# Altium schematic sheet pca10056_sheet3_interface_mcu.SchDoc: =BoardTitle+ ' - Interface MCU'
size A3; Organization: Nordic Semiconductor; DocumentNumber: 3; SheetNumber: 3; SheetTotal: 6; CompanyName: Nordic Semiconductor; DocumentSize: A3
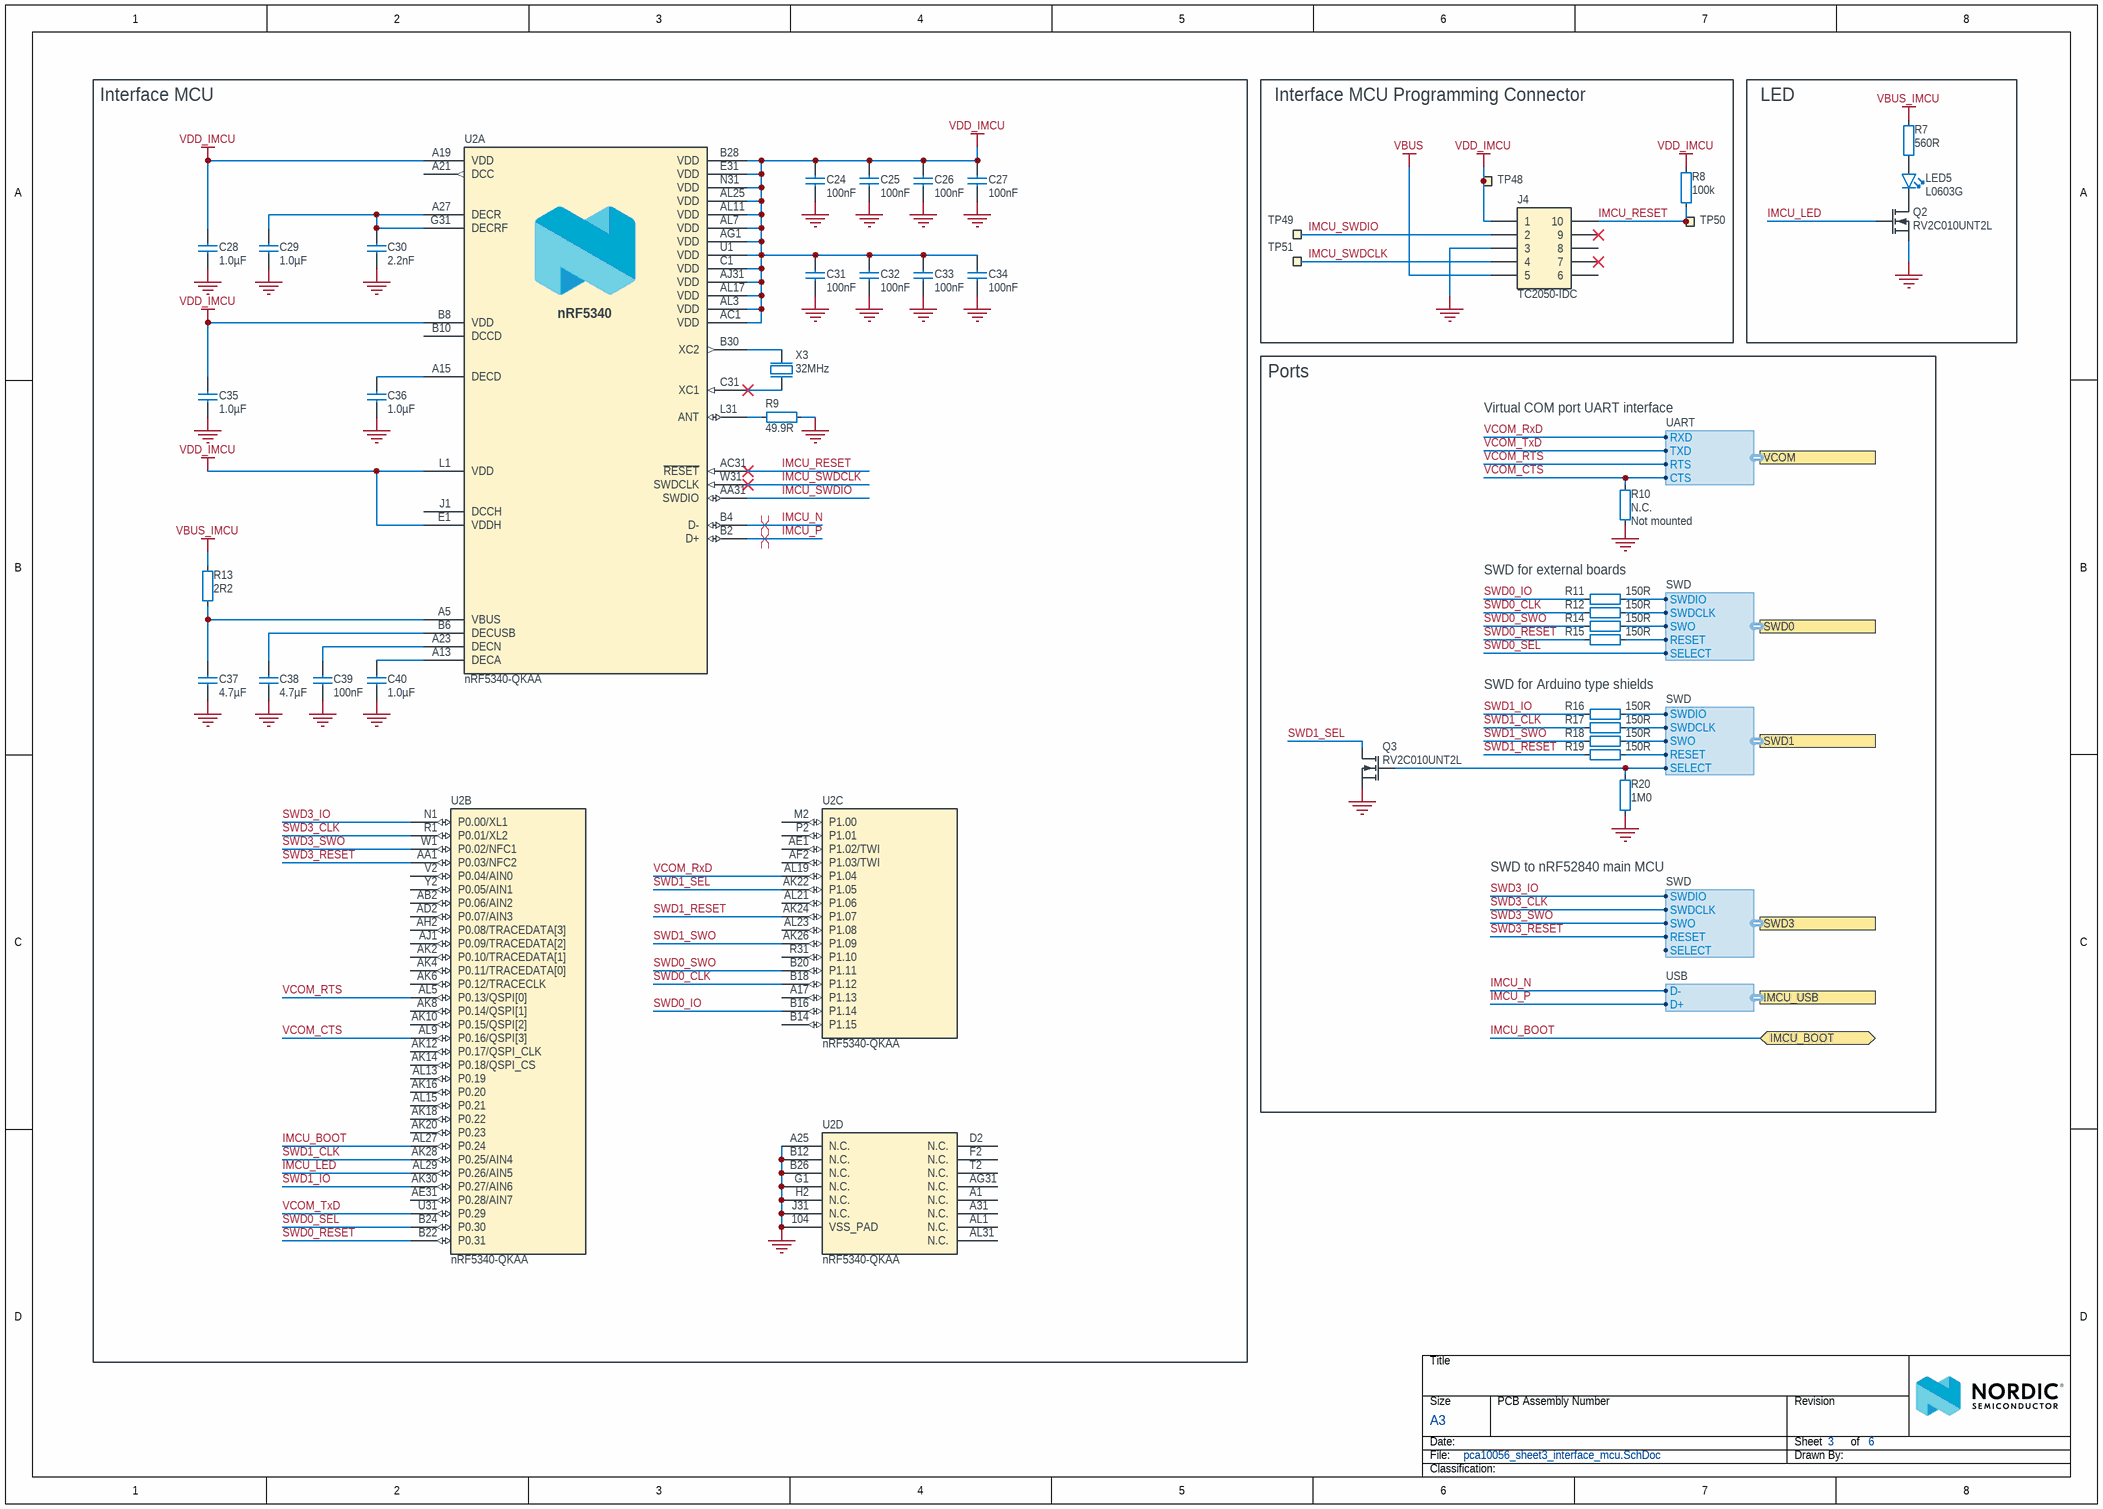
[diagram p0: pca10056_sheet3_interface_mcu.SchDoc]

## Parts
C24  100nF  [CAPC0603X03L_C]
C25  100nF  [CAPC0603X03L_C]
C26  100nF  [CAPC0603X03L_C]
C27  100nF  [CAPC0603X03L_C]
C28  1.0µF  [CAPC1005X04L]
C29  1.0µF  [CAPC1005X04L]
C30  2.2nF  [CAPC0603X03L_C]
C31  100nF  [CAPC0603X03L_C]
C32  100nF  [CAPC0603X03L_C]
C33  100nF  [CAPC0603X03L_C]
C34  100nF  [CAPC0603X03L_C]
C35  1.0µF  [CAPC1005X04L]
C36  1.0µF  [CAPC1005X04L]
C37  4.7µF  [CAPC1608X06L]
C38  4.7µF  [CAPC1608X06L]
C39  100nF  [CAPC0603X03L_C]
C40  1.0µF  [CAPC1005X04L]
J4  TC2050-IDC  [TC2050-IDC-NLFP]  (no BOM)
LED5  L0603G  [LED_0603_G]
Q2  RV2C010UNT2L  [DFN65P100X40-3L]
Q3  RV2C010UNT2L  [DFN65P100X40-3L]
R7  560R  [RESC0603X03L_C]
R8  100k  [RESC0603X03L_C]
R9  49.9R  [RESC0603X03L_C]
R10  N.C.  Assembly: Not mounted  [RESC0603X03L_C_NC]
R11  150R  [RESC0603X03L_C]
R12  150R  [RESC0603X03L_C]
R13  2R2  [RESC0603X03L_C]
R14  150R  [RESC0603X03L_C]
R15  150R  [RESC0603X03L_C]
R16  150R  [RESC0603X03L_C]
R17  150R  [RESC0603X03L_C]
R18  150R  [RESC0603X03L_C]
R19  150R  [RESC0603X03L_C]
R20  1M0  [RESC0603X03L_C]
TP48  Ø1.5mm,SMD  [TP_SMD_D1.5mm]  (value not drawn)  (no BOM)
TP49  Ø1.5mm,SMD  [TP_SMD_D1.5mm]  (value not drawn)  (no BOM)
TP50  Ø1.5mm,SMD  [TP_SMD_D1.5mm]  (value not drawn)  (no BOM)
TP51  Ø1.5mm,SMD  [TP_SMD_D1.5mm]  (value not drawn)  (no BOM)
U2  nRF5340-QKAA  [AQFN40P700X700X85_HS-99N]  (parts A,B,C,D of 4)
X3  32MHz  [BT-XTAL_2016]

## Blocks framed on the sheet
Interface MCU: C24-C40 R9 R13 U2 X3
Interface MCU Programming Connector: J4 R8 TP48-TP51
LED: LED5 Q2 R7
Ports: Q3 R10-R12 R14-R20

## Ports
IMCU_BOOT (bidir), IMCU_USB (harness USB), SWD0 (harness SWD), SWD1 (harness SWD), SWD3 (harness SWD), VCOM (harness UART)

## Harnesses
UART: RTS, CTS, RXD, TXD
SWD: SWDIO, SWDCLK, SWO, RESET, SELECT
USB: D+, D-

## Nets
GND: C24.2 C25.2 C26.2 C27.2 C28.2 C29.1 C30.2 C31.2 C32.2 C33.2 C34.2 C35.1 C36.1 C37.2 C38.2 C39.2 C40.1 J4.3 Q2.2(S) Q3.2(S) R9.2 R10.2 R20.2 U2.104(VSS_PAD) U2.A25(N.C.) U2.B12(N.C.) U2.B26(N.C.) U2.G1(N.C.) U2.H2(N.C.) U2.J31(N.C.) X3.2(GND) X3.4(GND)
VBUS: J4.5
VBUS_IMCU: R7.2 R13.1
VDD_IMCU: C24.1 C25.1 C26.1 C27.1 C28.1 C31.1 C32.1 C33.1 C34.1 C35.2 J4.1 R8.2 TP48.1 U2.A19(VDD) U2.AC1(VDD) U2.AG1(VDD) U2.AJ31(VDD) U2.AL3(VDD) U2.AL7(VDD) U2.AL11(VDD) U2.AL17(VDD) U2.AL25(VDD) U2.B8(VDD) U2.B28(VDD) U2.C1(VDD) U2.E1(VDDH) U2.E31(VDD) U2.L1(VDD) U2.N31(VDD) U2.U1(VDD)
IMCU_BOOT: U2.AL27(P0.24) ; port IMCU_BOOT
IMCU_LED: Q2.1(G) U2.AL29(P0.26/AIN5)
IMCU_N: U2.B4(D-) ; port IMCU_USB.D-
IMCU_P: U2.B2(D+) ; port IMCU_USB.D+
IMCU_RESET: J4.10 R8.1 TP50.1 U2.AC31(~{RESET})
IMCU_SWDCLK: J4.4 TP51.1 U2.W31(SWDCLK)
IMCU_SWDIO: J4.2 TP49.1 U2.AA31(SWDIO)
SWD0_CLK: R12.1 U2.B18(P1.12)
SWD0_IO: R11.1 U2.B16(P1.14)
SWD0_RESET: R15.1 U2.B22(P0.31)
SWD0_SEL: U2.B24(P0.30) ; port SWD0.SELECT
SWD0_SWO: R14.1 U2.B20(P1.11)
SWD1_CLK: R17.1 U2.AK28(P0.25/AIN4)
SWD1_IO: R16.1 U2.AK30(P0.27/AIN6)
SWD1_RESET: R19.1 U2.AK24(P1.07)
SWD1_SEL: Q3.3(D) U2.AK22(P1.05)
SWD1_SWO: R18.1 U2.AK26(P1.09)
SWD3_CLK: U2.R1(P0.01/XL2) ; port SWD3.SWDCLK
SWD3_IO: U2.N1(P0.00/XL1) ; port SWD3.SWDIO
SWD3_RESET: U2.AA1(P0.03/NFC2) ; port SWD3.RESET
SWD3_SWO: U2.W1(P0.02/NFC1) ; port SWD3.SWO
VCOM_CTS: R10.1 U2.AL9(P0.16/QSPI[3]) ; port VCOM.CTS
VCOM_RTS: U2.AL5(P0.13/QSPI[0]) ; port VCOM.RTS
VCOM_RxD: U2.AL19(P1.04) ; port VCOM.RXD
VCOM_TxD: U2.U31(P0.29) ; port VCOM.TXD
NetC29_2: C29.2 C30.1 U2.A27(DECR) U2.G31(DECRF)
NetC36_2: C36.2 U2.A15(DECD)
NetC37_1: C37.1 R13.2 U2.A5(VBUS)
NetC38_1: C38.1 U2.B6(DECUSB)
NetC39_1: C39.1 U2.A23(DECN)
NetC40_2: C40.2 U2.A13(DECA)
NetLED5_1: LED5.1(C) Q2.3(D)
NetLED5_2: LED5.2(A) R7.1
NetQ3_1: Q3.1(G) R20.1 ; port SWD1.SELECT
NetR9_1: R9.1 U2.L31(ANT)
NetR11_2: R11.2 ; port SWD0.SWDIO
NetR12_2: R12.2 ; port SWD0.SWDCLK
NetR14_2: R14.2 ; port SWD0.SWO
NetR15_2: R15.2 ; port SWD0.RESET
NetR16_2: R16.2 ; port SWD1.SWDIO
NetR17_2: R17.2 ; port SWD1.SWDCLK
NetR18_2: R18.2 ; port SWD1.SWO
NetR19_2: R19.2 ; port SWD1.RESET
NetU2_B30: U2.B30(XC2) X3.3(out)
NetU2_C31: U2.C31(XC1) X3.1(inp)

Not connected (* = marked no-connect by the designer): J4 6 7* 8 9*; U2 A1(N.C.) A17(P1.13) A21(DCC) A31(N.C.) AB2(P0.06/AIN2) AD2(P0.07/AIN3) AE1(P1.02/TWI) AE31(P0.28/AIN7) AF2(P1.03/TWI) AG31(N.C.) AH2(P0.08/TRACEDATA[3]) AJ1(P0.09/TRACEDATA[2]) AK2(P0.10/TRACEDATA[1]) AK4(P0.11/TRACEDATA[0]) AK6(P0.12/TRACECLK) AK8(P0.14/QSPI[1]) AK10(P0.15/QSPI[2]) AK12(P0.17/QSPI_CLK) AK14(P0.18/QSPI_CS) AK16(P0.20) AK18(P0.22) AK20(P0.23) AL1(N.C.) AL13(P0.19) AL15(P0.21) AL21(P1.06) AL23(P1.08) AL31(N.C.) B10(DCCD) B14(P1.15) D2(N.C.) F2(N.C.) J1(DCCH) M2(P1.00) P2(P1.01) R31(P1.10) T2(N.C.) V2(P0.04/AIN0) Y2(P0.05/AIN1)

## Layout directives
differential pair: IMCU_N, IMCU_P

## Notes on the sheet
- Virtual COM port UART interface
- SWD for external boards
- SWD for Arduino type shields
- (near R20) SWD to nRF52840 main MCU

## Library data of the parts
C24-C27 C31-C34 C39 = C0201-100n: Capacitor, X5R, ±10%; Manufacturer: N.A.; Part number IPS: 00000001248, 00000002505; Part number Norautron: 262071862; Part number NEMS: 100200078; Pad Count: 2; Note: 16V; Component Status: Active
C28 C29 C35 C36 C40 = C0402-1µ0-6.3V-X5R-10%: Capacitor, X5R, ±10%, 6.3V; Manufacturer: N.A.; Part number Norautron: 26207137; Part number NEMS: 100200498; Pad Count: 2; Component Status: Active
C30 = C0201-2n2: Capacitor, X7R, ±10%, 10V; Manufacturer: N.A.; Part number IPS: 00000001778; Part number Norautron: 26470002; Part number NEMS: 100200060; Pad Count: 2; Component Status: Active
C37 = C0603-4µ7-10V-X7S: Capacitor, X7S, ±10%, 10V; Manufacturer: N.A.; Part number IPS: 00000001779; Part number NEMS: 100200351; Pad Count: 2; Artikkelnr Noca: 20030013; Component Status: Active
C38 = C0603-4µ7-6.3V-X7R: Capacitor, X7R, ±10%, 6.3V; Manufacturer: Samsung Electro-Mechanics America; Manufacturer Part Number: CL10B475KQ8NQNC; Part number IPS: 00000002541; Part number Norautron: N.A.; Part number NEMS: 100200350; Pad Count: 2; Artikkelnr Noca: 20039473; Component Status: Active
J4 = TC2050-IDC-NLFP: CBL PLUG-OF-NAILS 10-PIN; Manufacturer: Tag-Connect LLC; Part number NEMS: 100500463; Artikkelnr Noca: N.A.; Pad Count: 10; Component Status: Active; System: Connector
LED5 = VS 25C7M5: LED, Green, 0603, 573nm, Vf=2.0V, 24mcd, - 40 to +85°C; Manufacturer: Victory Electronics; Part number IPS: 00000001274, 00000009961; Part number Norautron: 26313411; Part number NEMS: 101400097; Note: N.A.; Artikkelnr Noca: 13019193; Pad Count: 2; Component Status: Active
Q2 Q3 = RV2C010UNT2L: N-Channel MOSFET, 20V, 1A, 470mOhm, 400mW; Manufacturer: Rohm Semiconductor; Part number IPS: 00000009976; Part number Norautron: 26320026; Part number NEMS: 101300132; Note: N.A.; Artikkelnr Noca: 35010020; Pad Count: 3; Component Status: Active
R7 = R0201-560: Resistor, ±1%, 0.05W; Manufacturer: N.A.; Part number NEMS: 100100038; Note: Chip Res 1%; Pad Count: 2; Component Status: Active
R8 = R0201-100k: Resistor, ±1%, 0.05W; Manufacturer: N.A.; Part number IPS: 00000001419; Part number Norautron: 26108487; Part number NEMS: 100100080; Note: Chip Res 1%; Pad Count: 2; Component Status: Active
R9 = R0201-49R9: Resistor, ±1%, 0.05W; Manufacturer: N.A.; Part number Norautron: 26107071; Part number NEMS: 100100612; Pad Count: 2; Note: Chip Res 1%; Component Status: Active
R10 = R0201-N.C.: Not mounted; Manufacturer: N.A.; Part number NEMS: 100100107; Note: Chip Res; Pad Count: 2; Component Status: Active
R11 R12 R14-R19 = R0201-150: Resistor, ±1%, 0.05W; Manufacturer: N.A.; Part number IPS: 00000001420; Part number NEMS: 100100029; Note: Chip Res 1%; Pad Count: 2; Component Status: Active
R13 = R0201-2R2: Resistor, ±1%, 0.05W; Manufacturer: N.A.; Part number Norautron: 26470029; Part number NEMS: 100100006; Pad Count: 2; Note: Chip Res 1%; Component Status: Active
R20 = R0201-1M0: Resistor, ±1%, 0.05W; Manufacturer: N.A.; Part number IPS: 00000001418; Part number Norautron: 26107108; Part number NEMS: 100100093; Note: Chip Res 1%; Pad Count: 2; Component Status: Active
TP48-TP51 = TP_SMD_Ø1.5MM: 1.5mm circular SMD testpad; Manufacturer: Nordic Semiconductor; Manufacturer Part Number: N.A.; Part number NEMS: 100500477; Pad Count: 1; Component Status: Active
U2 = nRF5340-QKAAD0: Multi-protocol Bluetooth Low Energy, IEEE 802.15.4, ANT and 2.4GHz proprietary system-on-chip; Manufacturer: Nordic Semiconductor; Part number Norautron: NOD26470035; Part number NEMS: 102000216; Pad Count: 98; Note: N.A.; Component Status: Active
X3 = XTAL_SMD2016_32MHz_8pF_Golledge_MP12308: XTAL SMD 2016, 32MHz, Cl=8pF, Tol: ±10ppm, Stab: ±15ppm, -30°C ~ 85°C, ESR: 50ohm max; Part number NEMS: 101600118,101600041; Note: XTAL SMD 32.000MHz; Artikkelnr Noca: N.A.; Pad Count: 4; Component Status: Active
